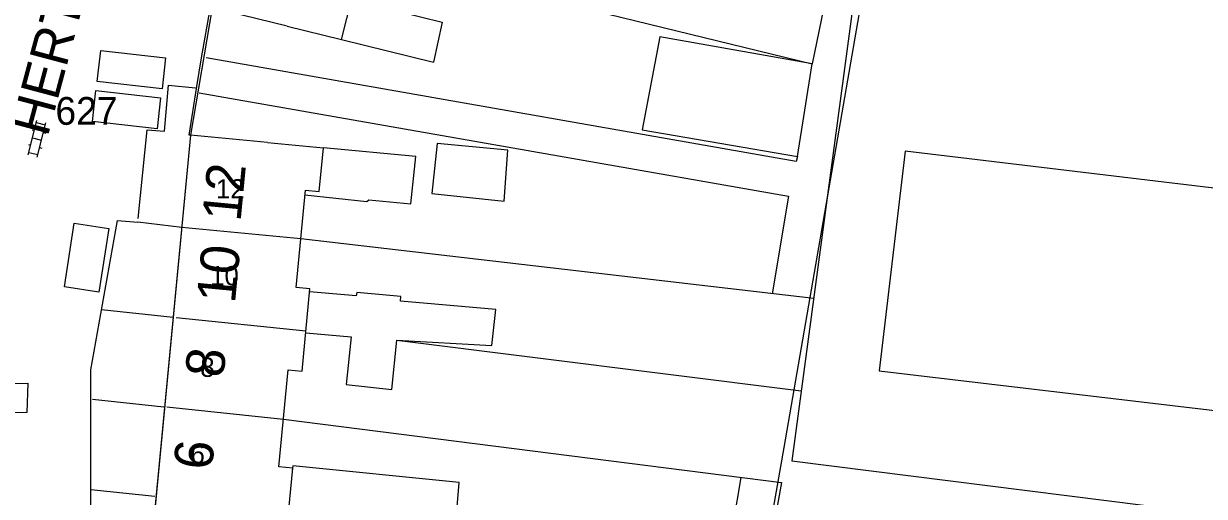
# Model space of a CAD drawing. Extents: x 148816 to 151297, y 399515 to 402500.
# Drawn here: x 149771.5 to 149847.9, y 400269.9 to 400300.6 of the extents above; entities that cross this region are included whole.
import ezdxf

# ---------------------------------------------------------------- set-up
doc = ezdxf.new("R2010")
doc.units = 0
for name, color, linetype in [('B01 Hoofdgebouw  [D] Norm', 7, 'Continuous'), ('B01 Hoofdgebouw  [T] Norm', 7, 'Continuous'), ('B01 hoofgebouw', 7, 'Continuous'), ('B07 Tussenmuur  [D] Norm', 7, 'Continuous'), ('G01 perceelsgrens', 7, 'Continuous'), ('S02 Open verharding  Norm', 7, 'Continuous'), ('T04 Haag heg  [D] Gem', 7, 'Continuous'), ('V00 Kant verharding algemeen  [T] Norm', 7, 'Continuous'), ('V00 Kant verharding algemeen secundair  [T] Gem', 7, 'Continuous'), ('Z01 perceelnummer', 7, 'Continuous'), ('Z02 huisnummer', 7, 'Continuous'), ('Z02 Huisnummer  [Tekst] Norm', 7, 'Continuous'), ('Z06 straatnaam', 7, 'Continuous')]:
    doc.layers.add(name, color=color, linetype=linetype)

msp = doc.modelspace()

# ---------------------------------------------------------------- linework, layer by layer
at = {"layer": 'B01 Hoofdgebouw  [D] Norm'}
msp.add_line((149788.58, 400300.39), (149792.102, 400299.528), dxfattribs=at)
for points in [[(149792.594, 400305.28), (149796.424, 400304.349), (149795.795, 400301.354), (149798.611, 400300.65), (149798.036, 400298.075)], [(149792.102, 400299.527), (149798.036, 400298.075)], [(149796.895, 400291.955), (149790.921, 400292.519)], [(149789.724, 400289.46), (149793.734, 400289.037), (149793.862, 400289.138), (149796.579, 400288.893), (149796.895, 400291.955)], [(149789.778, 400280.522), (149792.712, 400280.273), (149792.387, 400277.174), (149795.358, 400276.851), (149795.683, 400280.052), (149801.829, 400279.71), (149802.073, 400282.047), (149795.903, 400282.567), (149795.93, 400282.872), (149793.086, 400283.143), (149793.034, 400282.915), (149790.032, 400283.189)], [(149788.421, 400266.281), (149791.325, 400266.046), (149791.322, 400265.69), (149800.031, 400264.875), (149800.279, 400267.771), (149799.467, 400267.954), (149799.714, 400270.825), (149788.949, 400271.907), (149788.896, 400271.602)]]:
    msp.add_lwpolyline(points, dxfattribs=at)
for points in [[(149811.548, 400293.683), (149821.598, 400291.945), (149822.551, 400297.964), (149812.705, 400299.701)], [(149797.929, 400289.545), (149802.626, 400289.06), (149802.851, 400292.363), (149798.281, 400292.797)]]:
    msp.add_lwpolyline(points, close=True, dxfattribs=at)
at = {"layer": 'B01 Hoofdgebouw  [T] Norm'}
for p, q in [((149788.58, 400300.39), (149783.72, 400301.58)), ((149782.33, 400293.33), (149778.97, 400258.14)), ((149787.31, 400292.86), (149782.33, 400293.33)), ((149787.31, 400292.86), (149790.922, 400292.519))]:
    msp.add_line(p, q, dxfattribs=at)
for points in [[(149792.102, 400299.528), (149792.777, 400302.285), (149791.913, 400302.497), (149793.41, 400308.613), (149794.274, 400308.401), (149795.548, 400313.605), (149794.675, 400313.819), (149796.172, 400319.935), (149797.046, 400319.721), (149798.322, 400324.934), (149797.448, 400325.148), (149798.941, 400331.245), (149799.815, 400331.031), (149800.492, 400333.798)], [(149787.56, 400257.25), (149787.83, 400260.085), (149786.932, 400260.171), (149787.534, 400266.49), (149788.433, 400266.404), (149788.943, 400271.755), (149788.044, 400271.841), (149788.643, 400278.12), (149789.541, 400278.034), (149790.051, 400283.385), (149789.153, 400283.47), (149789.754, 400289.78), (149790.653, 400289.694), (149790.922, 400292.519)]]:
    msp.add_lwpolyline(points, dxfattribs=at)
msp.add_lwpolyline([(149871.627, 400289.79), (149853.905, 400291.923), (149853.588, 400289.292), (149828.569, 400292.306), (149826.88, 400278.063), (149869.606, 400273.002)], close=True, dxfattribs=at)
at = {"layer": 'B01 hoofgebouw'}
for points in [[(149788.58, 400300.39), (149783.72, 400301.58), (149792.11, 400335.85), (149796.97, 400334.66)], [(149792.102, 400299.528), (149792.777, 400302.285), (149791.913, 400302.497), (149793.41, 400308.613), (149794.274, 400308.401), (149795.548, 400313.605), (149794.675, 400313.819), (149796.172, 400319.935), (149797.046, 400319.721), (149798.322, 400324.934), (149797.448, 400325.148), (149798.941, 400331.245), (149799.815, 400331.031), (149800.492, 400333.798)], [(149788.58, 400300.39), (149792.102, 400299.528)], [(149787.31, 400292.86), (149782.33, 400293.33), (149778.97, 400258.14), (149793.41, 400256.64), (149793.72, 400259.63)], [(149787.56, 400257.25), (149787.83, 400260.085), (149786.932, 400260.171), (149787.534, 400266.49), (149788.433, 400266.404), (149788.943, 400271.755), (149788.044, 400271.841), (149788.643, 400278.12), (149789.541, 400278.034), (149790.051, 400283.385), (149789.153, 400283.47), (149789.754, 400289.78), (149790.653, 400289.694), (149790.922, 400292.519)], [(149787.31, 400292.86), (149790.922, 400292.519)]]:
    msp.add_lwpolyline(points, dxfattribs=at)
at = {"layer": 'B07 Tussenmuur  [D] Norm'}
for p, q in [((149789.453, 400286.623), (149781.759, 400287.357)), ((149789.453, 400286.623), (149781.759, 400287.357)), ((149781.393, 400281.526), (149789.791, 400280.656)), ((149781.393, 400281.526), (149789.791, 400280.656)), ((149780.791, 400275.72), (149788.339, 400274.938)), ((149780.791, 400275.72), (149788.339, 400274.938))]:
    msp.add_line(p, q, dxfattribs=at)
at = {"layer": 'G01 perceelsgrens'}
for points in [[(149804.63, 400366.51), (149796.669, 400353.941), (149792.11, 400335.85), (149783.72, 400301.58), (149782.33, 400293.33), (149778.97, 400258.14), (149777.994, 400258.284), (149777.996, 400247.375), (149778.543, 400230.381), (149779.311, 400220.249), (149779.578, 400218.899), (149779.904, 400218.147), (149780.264, 400217.642), (149780.697, 400217.304), (149781.244, 400217.051), (149781.723, 400216.858), (149783.212, 400216.808)], [(149825.415, 400300.146), (149825.586, 400301.131), (149828.356, 400317.096), (149853.483, 400300.138), (149854.231, 400298.37)], [(149820.73, 400273.09), (149825.415, 400300.146)], [(149819.195, 400264.227), (149820.73, 400273.09)]]:
    msp.add_lwpolyline(points, dxfattribs=at)
at = {"layer": 'S02 Open verharding  Norm'}
for p, q in [((149771.815, 400292.053), (149772.382, 400294.281)), ((149772.926, 400293.988), (149772.345, 400294.136)), ((149772.396, 400291.905), (149772.963, 400294.133)), ((149772.076, 400293.689), (149772.222, 400293.652)), ((149772.803, 400293.504), (149772.948, 400293.467)), ((149771.83, 400292.719), (149771.975, 400292.682)), ((149772.098, 400293.167), (149772.68, 400293.019)), ((149772.556, 400292.534), (149772.702, 400292.497)), ((149772.433, 400292.05), (149771.852, 400292.198))]:
    msp.add_line(p, q, dxfattribs=at)
at = {"layer": 'T04 Haag heg  [D] Gem'}
for p, q in [((149824.215, 400305.979), (149822.551, 400297.964)), ((149796.424, 400304.349), (149822.551, 400297.964)), ((149821.528, 400291.638), (149783.338, 400298.352)), ((149782.89, 400296.067), (149821.029, 400289.378)), ((149821.598, 400291.945), (149821.528, 400291.638)), ((149821.029, 400289.378), (149819.974, 400283.056)), ((149822.65, 400282.754), (149789.453, 400286.623)), ((149776.57, 400282.026), (149781.205, 400281.546)), ((149795.683, 400280.052), (149821.85, 400276.769)), ((149775.969, 400276.219), (149780.604, 400275.739)), ((149788.339, 400274.938), (149820.566, 400270.834)), ((149817.935, 400271.159), (149815.741, 400258.337))]:
    msp.add_line(p, q, dxfattribs=at)
msp.add_lwpolyline([(149820.566, 400270.834), (149818.13, 400257.28)], dxfattribs=at)
at = {"layer": 'V00 Kant verharding algemeen  [T] Norm'}
for p, q in [((149783.03, 400298.34), (149783.61, 400301.62)), ((149782.73, 400296.48), (149783.03, 400298.34)), ((149782.23, 400293.34), (149782.73, 400296.48)), ((149782.33, 400293.33), (149782.23, 400293.34)), ((149781.759, 400287.357), (149778.918, 400287.706)), ((149775.865, 400270.361), (149780.002, 400269.933))]:
    msp.add_line(p, q, dxfattribs=at)
for points in [[(149855.196, 400291.768), (149853.333, 400300.181), (149850.786, 400301.884), (149825.66, 400305.246), (149821.242, 400272.229), (149844.178, 400269.335), (149853.581, 400236.253)], [(149775.865, 400270.361), (149775.869, 400278.116), (149777.604, 400287.794), (149778.918, 400287.706)], [(149765.553, 400277.21), (149771.796, 400277.257), (149771.727, 400275.355), (149765.535, 400275.333), (149765.528, 400277.21)]]:
    msp.add_lwpolyline(points, dxfattribs=at)
at = {"layer": 'V00 Kant verharding algemeen secundair  [T] Gem'}
for points in [[(149776.511, 400298.81), (149780.701, 400298.346), (149780.479, 400296.338), (149776.289, 400296.802)], [(149776.19, 400296.221), (149780.38, 400295.757), (149780.158, 400293.749), (149775.968, 400294.213)], [(149777.036, 400287.295), (149776.396, 400283.16), (149774.157, 400283.506), (149774.797, 400287.641)]]:
    msp.add_lwpolyline(points, close=True, dxfattribs=at)
for points in [[(149778.942, 400287.944), (149779.512, 400293.684), (149780.642, 400293.585), (149780.898, 400296.571), (149782.643, 400296.403)], [(149776.668, 400264.41), (149776.896, 400266.684), (149775.864, 400266.809), (149775.865, 400270.361)]]:
    msp.add_lwpolyline(points, dxfattribs=at)

# ---------------------------------------------------------------- texts
at = {"layer": 'Z01 perceelnummer'}
msp.add_text('627', height=1.8, dxfattribs=at).set_placement((149773.58, 400294.006))
at = {"layer": 'Z02 huisnummer'}
for s, p in [('12', (149785.558, 400287.687)), ('10', (149785.198, 400282.389)), ('8', (149784.454, 400277.574)), ('6', (149783.707, 400271.59))]:
    msp.add_text(s, height=2.5, rotation=84.54608, dxfattribs=at).set_placement(p)
at = {"layer": 'Z02 Huisnummer  [Tekst] Norm'}
for s, p in [('12', (149783.964, 400289.231)), ('10', (149783.589, 400283.6)), ('8', (149782.956, 400277.669)), ('6', (149782.322, 400272.049))]:
    msp.add_text(s, height=1.25, dxfattribs=at).set_placement(p)
at = {"layer": 'Z06 straatnaam'}
msp.add_text('HERTOGENSTRAAT', height=2.5, rotation=75.04644, dxfattribs=at).set_placement((149773.074, 400293.175))

doc.saveas('drawing.dxf')
